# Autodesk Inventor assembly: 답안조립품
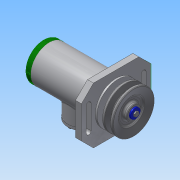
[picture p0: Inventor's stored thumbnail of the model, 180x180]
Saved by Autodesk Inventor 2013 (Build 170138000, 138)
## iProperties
Created: 2017-10
Part Number: 답안조립품
Document SubType Name: Assembly
Designer: Administrator
Author: Administrator
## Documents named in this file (20)
- C:\Users\Administrator\Desktop\471008V1012\답안조립품.iam
- C:\Users\Administrator\Desktop\471008V1012\본체.ipt
- C:\Users\Administrator\Desktop\471008V1012\V-벨트풀리.ipt
- C:\Users\Administrator\Desktop\471008V1012\너트 M10.ipt
- C:\Users\Administrator\Desktop\471008V1012\멈춤링 15 x 1.ipt
- C:\Users\Administrator\Desktop\471008V1012\멈춤링 35x1.6.ipt
- C:\Users\Administrator\Desktop\471008V1012\베어링 15 x 35 x 11.ipt
- C:\Users\Administrator\Desktop\471008V1012\볼트 M4 x 10.ipt
- C:\Users\Administrator\Desktop\471008V1012\부시1.ipt
- C:\Users\Administrator\Desktop\471008V1012\부시2.ipt
- C:\Users\Administrator\Desktop\471008V1012\사이드 커버.ipt
- 사이드 커버.ipt
- C:\Users\Administrator\Desktop\471008V1012\십자볼트 M3 x 10.ipt
- C:\Users\Administrator\Desktop\471008V1012\오일 실 15 25 7.ipt
- C:\Users\Administrator\Desktop\471008V1012\와셔 3x6.ipt
- C:\Users\Administrator\Desktop\471008V1012\와셔 4x16.ipt
- C:\Users\Administrator\Desktop\471008V1012\와셔 10x21.ipt
- C:\Users\Administrator\Desktop\471008V1012\축.ipt
- C:\Users\Administrator\Desktop\471008V1012\키 4 x 4 x 18.ipt
- C:\Users\Administrator\Desktop\471008V1012\탑 커버.ipt
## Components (2 placed, 2 different names)
1. V-벨트풀리:1
2. ISO 4017 M4 x 10:1
